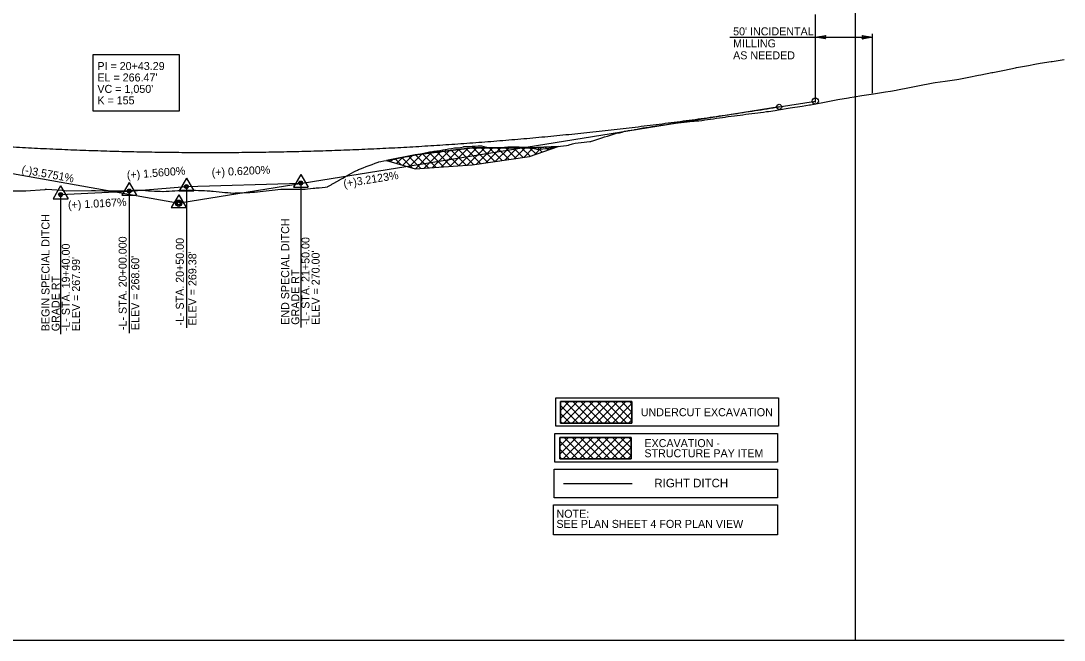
# Model space of a CAD drawing. Extents: x 10000 to 11818, y 10000 to 11025.
# Drawn here: x 10905 to 11818, y 10000 to 10542 of the extents above; entities that cross this region are included whole.
import ezdxf

# ---------------------------------------------------------------- set-up
doc = ezdxf.new("R2010")
doc.units = 0
for name, color, linetype in [('Exist Profile Cell', 7, 'Continuous'), ('Exist Vertical Profile Ground Line', 7, 'Continuous'), ('Old_Level_1', 7, 'Continuous'), ('Prop Grid Mask', 7, 'Continuous'), ('Prop PFL Ditch Label CELL', 7, 'Continuous'), ('Prop PFL VPI Symbol CELL', 7, 'Continuous'), ('Prop Terminator CELL', 7, 'Continuous'), ('Prop Vertical Profile Curve Label', 7, 'Continuous'), ('Prop Vertical Profile Ditch Grade Right', 7, 'Continuous'), ('Prop Vertical Profile Ditch Grade Right Label', 7, 'Continuous'), ('Prop Vertical Profile Grade', 7, 'Continuous'), ('Prop Vertical Profile Grade Label', 7, 'Continuous'), ('Prop VPI Ditch Grade Right Label', 7, 'Continuous'), ('Prop VPI Label', 7, 'Continuous'), ('Sheet Layout Profile Border', 7, 'Continuous'), ('Sheet Profile Grid Minor CELL', 7, 'Continuous')]:
    doc.layers.add(name, color=color, linetype=linetype)

msp = doc.modelspace()

# ---------------------------------------------------------------- linework, layer by layer
at = {"layer": 'Exist Profile Cell'}
msp.add_line((10000, 10000), (11817.54, 10000), dxfattribs=at)
at = {"layer": 'Exist Vertical Profile Ground Line'}
msp.add_lwpolyline([(10889.89, 10393.08), (10908.66, 10393.17), (10909.57, 10393.24), (10926.11, 10394.31), (10926.5, 10394.43), (10926.87, 10394.49), (10927.62, 10394.76), (10941.38, 10393.87), (10945.35, 10393.2), (10967.09, 10393.44), (10968.59, 10393.36), (10970.53, 10393.37), (10978.2, 10393.26), (10980.78, 10393.23), (10983.35, 10393.19), (10985.92, 10393.15), (10988.76, 10393.11), (10991.07, 10393.15), (10993.83, 10393.19), (10996.22, 10393.3), (10998.79, 10393.41), (11001.37, 10393.53), (11003.94, 10393.64), (11006.51, 10393.76), (11009.09, 10393.86), (11011.66, 10393.64), (11014.23, 10393.42), (11016.81, 10393.2), (11018, 10393.09), (11019.38, 10393.05), (11021.95, 10392.96), (11024.53, 10392.88), (11027.1, 10392.79), (11029.31, 10392.71), (11029.68, 10392.73), (11032.25, 10392.88), (11034.82, 10393.02), (11037.4, 10393.17), (11039.97, 10393.31), (11042.54, 10393.45), (11043.22, 10393.49), (11045.12, 10393.61), (11047.69, 10393.77), (11049.72, 10393.9), (11050.27, 10393.9), (11052.84, 10393.87), (11053.95, 10393.86), (11055.41, 10393.81), (11057.99, 10393.7), (11060.56, 10393.6), (11063.13, 10393.49), (11065.71, 10393.38), (11068.28, 10393.27), (11070.54, 10393.22), (11070.85, 10393.18), (11072.05, 10393.01), (11073.43, 10392.88), (11076, 10392.62), (11078.58, 10392.36), (11081.15, 10392.1), (11083.72, 10391.85), (11086.3, 10391.58), (11088.29, 10391.38), (11088.87, 10391.32), (11090.65, 10391.12), (11091.44, 10391.19), (11092.61, 10391.3), (11094.02, 10391.35), (11096.59, 10391.44), (11099.16, 10391.53), (11101.74, 10391.62), (11104.31, 10391.71), (11105.4, 10391.75), (11106.89, 10391.88), (11109.46, 10392.11), (11111.66, 10392.3), (11112.03, 10392.34), (11114.61, 10392.64), (11117.18, 10392.94), (11119.75, 10393.24), (11122.33, 10393.54), (11124.9, 10393.83), (11127.48, 10394.12), (11130.05, 10394.3), (11132.62, 10394.49), (11135.2, 10394.55), (11137.77, 10394.61), (11140.34, 10394.67), (11142.92, 10394.73), (11143.76, 10394.75), (11145.49, 10394.75), (11148.06, 10394.74), (11150.64, 10394.72), (11153.21, 10394.71), (11153.7, 10394.71), (11155.79, 10394.92), (11158.36, 10395.17), (11160.93, 10395.42), (11162.16, 10395.54), (11163.51, 10395.67), (11166.08, 10395.92), (11168.65, 10396.16), (11171.23, 10396.4), (11173.27, 10396.6), (11173.8, 10396.87), (11176.58, 10398.28), (11177.23, 10399.02), (11178.95, 10399.97), (11181.52, 10401.39), (11184.1, 10402.82), (11184.46, 10403.02), (11186.67, 10404.26), (11189.24, 10405.71), (11191.82, 10407.15), (11194.39, 10408.6), (11196.5, 10409.79), (11196.96, 10410.08), (11197.6, 10410.49), (11199.54, 10411.35), (11200.56, 10411.81), (11202.11, 10412.4), (11204.69, 10413.39), (11207.26, 10414.37), (11209.83, 10415.36), (11212.41, 10416.34), (11214.98, 10417.32), (11217.55, 10418.3), (11218.23, 10418.56), (11220.13, 10418.88), (11222.7, 10419.33), (11225.27, 10419.77), (11227.85, 10420.21), (11230.42, 10420.65), (11232.13, 10420.95), (11233, 10421.14), (11235.57, 10421.7), (11238.14, 10422.26), (11240.22, 10422.71), (11240.72, 10422.8), (11243.29, 10423.3), (11245.86, 10423.8), (11248.44, 10424.3), (11249.27, 10424.46), (11251.01, 10424.82), (11253.58, 10425.36), (11256.16, 10425.89), (11258.73, 10426.42), (11261.31, 10426.95), (11262.49, 10427.2), (11263.88, 10427.41), (11266.45, 10427.8), (11269.03, 10428.19), (11271.6, 10428.58), (11274.17, 10428.97), (11276.15, 10429.27), (11276.75, 10429.37), (11279.32, 10429.82), (11281.9, 10430.26), (11284.47, 10430.7), (11285.06, 10430.8), (11287.04, 10430.71), (11287.69, 10430.69), (11289.62, 10431.14), (11292.19, 10431.74), (11292.71, 10431.86), (11294.76, 10431.96), (11297.34, 10432.08), (11299.91, 10432.19), (11302.48, 10432.31), (11305.06, 10432.42), (11307.63, 10432.53), (11307.96, 10432.54), (11310.21, 10432.04), (11312.78, 10431.48), (11315.35, 10430.9), (11316.69, 10430.61), (11317.93, 10430.69), (11320.5, 10430.87), (11323.07, 10431.04), (11325.65, 10431.22), (11328.22, 10431.39), (11331.07, 10431.58), (11331.4, 10431.63), (11332.44, 10431.63), (11333.37, 10431.62), (11335.94, 10431.6), (11338.52, 10431.57), (11341.09, 10431.54), (11343.66, 10431.51), (11346.24, 10431.47), (11346.75, 10431.47), (11348.81, 10431.09), (11351.38, 10430.62), (11353.96, 10430.14), (11355.68, 10429.82), (11356.53, 10429.67), (11357.91, 10429.41), (11359.11, 10429.56), (11361.68, 10429.89), (11364.25, 10430.21), (11366.83, 10430.54), (11368.02, 10430.69), (11369.4, 10430.94), (11371.97, 10431.42), (11373.3, 10431.67), (11374.55, 10431.83), (11377.12, 10432.17), (11379.69, 10432.51), (11382.27, 10432.84), (11384.03, 10433.06), (11384.84, 10433.37), (11387.66, 10434.43), (11389.99, 10434.74), (11392.56, 10435.07), (11395.14, 10435.4), (11397.71, 10435.72), (11400.28, 10436.04), (11402.86, 10436.34), (11403.63, 10436.43), (11404.29, 10436.64), (11405.43, 10437.01), (11408, 10437.85), (11410.58, 10438.68), (11413.15, 10439.5), (11415.73, 10440.32), (11418.3, 10441.12), (11420.89, 10441.93), (11423.45, 10442.8), (11426.08, 10443.5), (11428.59, 10443.96), (11430.01, 10444.21), (11431.17, 10444.62), (11433.17, 10445.33), (11433.74, 10445.42), (11436.32, 10445.82), (11438.89, 10446.22), (11441.46, 10446.62), (11442.11, 10446.72), (11444.04, 10447.19), (11446.52, 10447.78), (11449.18, 10448.2), (11451.76, 10448.6), (11454.33, 10449), (11456.9, 10449.4), (11459.48, 10449.79), (11461.16, 10450.05), (11462.05, 10450.18), (11464.63, 10450.57), (11467.2, 10450.95), (11469.77, 10451.33), (11472.35, 10451.7), (11474.92, 10452.08), (11476.55, 10452.32), (11477.49, 10452.42), (11480.07, 10452.69), (11482.64, 10452.95), (11485.21, 10453.22), (11487.79, 10453.48), (11490.36, 10453.75), (11492.94, 10454.01), (11494.15, 10454.13), (11495.51, 10454.28), (11498.08, 10454.56), (11500.66, 10454.84), (11502.24, 10455.01), (11503.23, 10455.16), (11505.8, 10455.53), (11508.38, 10455.9), (11510.95, 10456.26), (11513.52, 10456.63), (11516.1, 10457), (11518.67, 10457.36), (11521.25, 10457.73), (11522.07, 10457.84), (11523.82, 10458.09), (11526.39, 10458.44), (11529.15, 10458.83), (11531.54, 10459.14), (11534.11, 10459.48), (11536.69, 10459.81), (11539.26, 10460.15), (11541.84, 10460.48), (11544.41, 10460.81), (11546.98, 10461.14), (11549.56, 10461.47), (11552.13, 10461.8), (11554.7, 10462.13), (11557.28, 10462.45), (11559.08, 10462.68), (11564.9, 10463.6), (11567.69, 10464.04), (11578.1, 10465.69), (11588.51, 10467.34), (11594.94, 10468.36), (11595.64, 10468.53), (11598.92, 10469.14), (11609.33, 10471.06), (11619.74, 10472.98), (11628.85, 10474.66), (11630.15, 10474.9), (11633.8, 10475.55), (11640.56, 10476.59), (11650.97, 10478.19), (11661.38, 10479.79), (11665.71, 10480.45), (11670.76, 10481.28), (11671.79, 10481.48), (11682.2, 10483.53), (11692.61, 10485.57), (11700.19, 10487.06), (11703.02, 10487.61), (11704.87, 10487.97), (11713.43, 10489.19), (11723.84, 10490.68), (11725.36, 10490.9), (11734.25, 10492.63), (11742.61, 10494.25), (11744.66, 10494.67), (11754.29, 10496.61), (11755.07, 10496.77), (11765.48, 10498.9), (11774.9, 10500.83), (11775.89, 10501.02), (11786.3, 10502.98), (11792.05, 10504.07), (11796.72, 10504.78), (11806.31, 10506.23), (11807.13, 10506.37), (11817.54, 10508.15)], dxfattribs=at)
at = {"layer": 'Old_Level_1'}
for p, q in [((11250, 10424.6), (11300, 10430.83)), ((11300, 10430.83), (11350, 10430.87)), ((11350, 10430.87), (11375, 10431.89)), ((11350, 10423.2), (11375, 10431.89)), ((11225, 10419.72), (11250, 10424.6)), ((11225, 10419.72), (11250, 10412.51)), ((11300, 10415.8), (11350, 10423.2)), ((11250, 10412.51), (11300, 10415.8)), ((11377.17, 10194.02), (11391.87, 10208.72)), ((11377.17, 10201.09), (11384.8, 10208.72)), ((11377.17, 10208.16), (11377.73, 10208.72)), ((11377.17, 10205.38), (11392.62, 10189.92)), ((11380.15, 10189.92), (11398.95, 10208.72)), ((11380.89, 10208.72), (11399.69, 10189.92)), ((11387.22, 10189.92), (11406.02, 10208.72)), ((11387.96, 10208.72), (11406.76, 10189.92)), ((11394.29, 10189.92), (11413.09, 10208.72)), ((11395.03, 10208.72), (11413.83, 10189.92)), ((11401.36, 10189.92), (11420.16, 10208.72)), ((11402.1, 10208.72), (11420.9, 10189.92)), ((11408.43, 10189.92), (11427.23, 10208.72)), ((11409.18, 10208.72), (11427.98, 10189.92)), ((11415.5, 10189.92), (11434.3, 10208.72)), ((11416.25, 10208.72), (11435.05, 10189.92)), ((11422.57, 10189.92), (11439.61, 10206.97)), ((11423.32, 10208.72), (11439.61, 10192.43)), ((11429.64, 10189.92), (11439.61, 10199.9)), ((11430.39, 10208.72), (11439.61, 10199.5)), ((11437.46, 10208.72), (11439.61, 10206.57)), ((11377.17, 10198.31), (11385.55, 10189.92)), ((11377.17, 10191.23), (11378.48, 10189.92)), ((11436.71, 10189.92), (11439.61, 10192.82)), ((11376.5, 10162.76), (11391.2, 10177.47)), ((11376.5, 10169.83), (11384.13, 10177.47)), ((11376.5, 10176.9), (11377.06, 10177.47)), ((11376.5, 10174.12), (11391.95, 10158.67)), ((11379.48, 10158.67), (11398.28, 10177.47)), ((11380.22, 10177.47), (11399.02, 10158.67)), ((11386.55, 10158.67), (11405.35, 10177.47)), ((11387.29, 10177.47), (11406.09, 10158.67)), ((11393.62, 10158.67), (11412.42, 10177.47)), ((11394.36, 10177.47), (11413.16, 10158.67)), ((11400.69, 10158.67), (11419.49, 10177.47)), ((11401.43, 10177.47), (11420.23, 10158.67)), ((11407.76, 10158.67), (11426.56, 10177.47)), ((11408.51, 10177.47), (11427.31, 10158.67)), ((11414.83, 10158.67), (11433.63, 10177.47)), ((11415.58, 10177.47), (11434.38, 10158.67)), ((11421.9, 10158.67), (11438.94, 10175.71)), ((11422.65, 10177.47), (11438.94, 10161.17)), ((11429.72, 10177.47), (11438.94, 10168.24)), ((11436.79, 10177.47), (11438.94, 10175.31)), ((11376.5, 10167.05), (11384.88, 10158.67)), ((11428.97, 10158.67), (11438.94, 10168.64)), ((11376.5, 10159.98), (11377.81, 10158.67)), ((11436.04, 10158.67), (11438.94, 10161.57))]:
    msp.add_line(p, q, dxfattribs=at)
for points in [[(11377.17, 10208.72), (11439.61, 10208.72), (11439.61, 10189.92), (11377.17, 10189.92)], [(11376.5, 10177.47), (11438.94, 10177.47), (11438.94, 10158.67), (11376.5, 10158.67)]]:
    msp.add_lwpolyline(points, close=True, dxfattribs=at)
for points in [[(11377.17, 10189.92), (11439.61, 10189.92), (11439.61, 10208.72), (11377.17, 10208.72), (11377.17, 10189.92)], [(11376.5, 10158.67), (11438.94, 10158.67), (11438.94, 10177.47), (11376.5, 10177.47), (11376.5, 10158.67)]]:
    msp.add_lwpolyline(points, dxfattribs=at)
at = {"layer": 'Prop Grid Mask'}
for points in [[(10968.58, 10512.58), (11043.68, 10512.58), (11043.68, 10462.87), (10968.58, 10462.87)], [(11372.97, 10212.13), (11567.63, 10212.13), (11567.63, 10187.13), (11372.97, 10187.13)], [(11372.3, 10180.88), (11566.96, 10180.88), (11566.96, 10155.88), (11372.3, 10155.88)], [(11371.63, 10149.62), (11566.96, 10149.62), (11566.96, 10124.62), (11371.63, 10124.62)], [(11370.96, 10118.36), (11566.96, 10118.36), (11566.96, 10092.28), (11370.96, 10092.28)]]:
    msp.add_lwpolyline(points, close=True, dxfattribs=at)
at = {"layer": 'Prop PFL Ditch Label CELL'}
for p, q in [((11372.97, 10197.13), (11372.97, 10197.13)), ((11372.3, 10165.88), (11372.3, 10165.88)), ((11379.71, 10136.97), (11439.71, 10136.97)), ((11371.63, 10134.62), (11371.63, 10134.62))]:
    msp.add_line(p, q, dxfattribs=at)
at = {"layer": 'Prop PFL VPI Symbol CELL'}
for p, q in [((10999.99, 10400.48), (10993.54, 10389.28)), ((10999.99, 10400.48), (11006.49, 10389.28)), ((11049.99, 10404.38), (11043.54, 10393.18)), ((11049.99, 10404.38), (11056.49, 10393.18)), ((11149.99, 10407.48), (11143.54, 10396.28)), ((11149.99, 10407.48), (11156.49, 10396.28)), ((10939.99, 10397.43), (10933.54, 10386.23)), ((10939.99, 10397.43), (10946.49, 10386.23)), ((11043.54, 10393.18), (11056.49, 10393.18)), ((11143.54, 10396.28), (11156.49, 10396.28)), ((10933.54, 10386.23), (10946.49, 10386.23)), ((10993.54, 10389.28), (11006.49, 10389.28)), ((11043.24, 10389.68), (11036.79, 10378.48)), ((11043.24, 10389.68), (11049.74, 10378.48)), ((11036.79, 10378.48), (11049.74, 10378.48))]:
    msp.add_line(p, q, dxfattribs=at)
for centre, radius in [((11150, 10400), 1.75), ((11150, 10400), 1.2), ((10940, 10389.95), 1.75), ((11000, 10393), 1.75), ((11000, 10393), 1.2), ((11050, 10396.9), 1.75), ((11050, 10396.9), 1.2), ((10940, 10389.95), 1.2), ((11043.25, 10382.2), 1.75), ((11043.25, 10382.2), 1.2)]:
    msp.add_circle(centre, radius, dxfattribs=at)
at = {"layer": 'Prop Terminator CELL'}
for points in [[(11609, 10526.04), (11600, 10527.59), (11609.05, 10529.19), (11607.9, 10527.59)], [(11641, 10529.14), (11650, 10527.59), (11640.95, 10525.99), (11642.1, 10527.59)]]:
    msp.add_lwpolyline(points, close=True, dxfattribs=at)
at = {"layer": 'Prop Vertical Profile Curve Label'}
msp.add_circle((11568.29, 10466.66), 2.25, dxfattribs=at)
at = {"layer": 'Prop Vertical Profile Ditch Grade Right'}
msp.add_lwpolyline([(10940, 10389.95), (11000, 10393), (11050, 10396.9), (11150, 10400)], dxfattribs=at)
at = {"layer": 'Prop Vertical Profile Ditch Grade Right Label'}
for p, q in [((11000, 10393), (11000, 10268.58)), ((11050, 10396.9), (11050, 10273.22)), ((11150, 10400), (11150, 10273.5)), ((10940, 10389.95), (10940, 10267.77))]:
    msp.add_line(p, q, dxfattribs=at)
at = {"layer": 'Prop Vertical Profile Grade'}
msp.add_line((11568.29, 10466.66), (11600, 10471.75), dxfattribs=at)
msp.add_spline([(10518.29, 10476.18), (10539.29, 10472.5), (10560.29, 10468.96), (10581.29, 10465.56), (10602.29, 10462.3), (10623.29, 10459.19), (10644.29, 10456.22), (10665.29, 10453.4), (10686.29, 10450.71), (10707.29, 10448.17), (10728.29, 10445.77), (10749.29, 10443.51), (10770.29, 10441.4), (10791.29, 10439.42), (10812.29, 10437.59), (10833.29, 10435.91), (10854.29, 10434.36), (10875.29, 10432.96), (10896.29, 10431.7), (10917.29, 10430.58), (10938.29, 10429.61), (10959.29, 10428.78), (10980.29, 10428.09), (11001.29, 10427.54), (11022.29, 10427.14), (11043.29, 10426.88), (11064.29, 10426.76), (11085.29, 10426.78), (11106.29, 10426.95), (11127.29, 10427.25), (11148.29, 10427.71), (11169.29, 10428.3), (11190.29, 10429.04), (11211.29, 10429.91), (11232.29, 10430.93), (11253.29, 10432.1), (11274.29, 10433.4), (11295.29, 10434.85), (11316.29, 10436.44), (11337.29, 10438.18), (11358.29, 10440.05), (11379.29, 10442.07), (11400.29, 10444.23), (11421.29, 10446.54), (11442.29, 10448.99), (11463.29, 10451.57), (11484.29, 10454.31), (11505.29, 10457.18), (11526.29, 10460.2), (11547.29, 10463.36), (11568.29, 10466.66)], degree=3, dxfattribs=at)
at = {"layer": 'Prop VPI Ditch Grade Right Label'}
for centre in [(11150, 10400), (10940, 10389.95)]:
    msp.add_circle(centre, 0.5, dxfattribs=at)
at = {"layer": 'Prop VPI Label'}
for p, q in [((11600, 10470.59), (11600, 10547.5)), ((11650, 10478.58), (11650, 10530.58)), ((11525.08, 10527.59), (11600, 10527.59)), ((11600, 10527.59), (11650, 10527.59)), ((10518.29, 10476.18), (11040.58, 10382.82)), ((11568.29, 10466.66), (11046.01, 10382.77))]:
    msp.add_line(p, q, dxfattribs=at)
for centre in [(11600, 10471.75), (11043.29, 10382.33)]:
    msp.add_circle(centre, 2.75, dxfattribs=at)
at = {"layer": 'Sheet Layout Profile Border'}
msp.add_lwpolyline([(10250, 11025), (10250, 10000), (10250, 10000), (11635, 10000), (11635, 10000), (11635, 10887.45), (11635, 10887.45), (11492.45, 10887.45), (11492.45, 11025)], close=True, dxfattribs=at)
at = {"layer": 'Sheet Profile Grid Minor CELL'}
for p, q in [((11300, 10430.83), (11250, 10424.6)), ((11265.33, 10413.51), (11280.17, 10428.36)), ((11272.9, 10414.01), (11288.25, 10429.36)), ((11275.42, 10427.77), (11288.17, 10415.02)), ((11280.47, 10414.51), (11296.33, 10430.37)), ((11281.71, 10428.55), (11294.81, 10415.45)), ((11288, 10429.33), (11301.34, 10415.99)), ((11288.04, 10415.01), (11303.86, 10430.83)), ((11294.29, 10430.11), (11307.5, 10416.91)), ((11295.61, 10415.51), (11310.94, 10430.83)), ((11350, 10430.87), (11300, 10430.83)), ((11300.65, 10430.83), (11313.66, 10417.82)), ((11303.48, 10416.31), (11318.01, 10430.84)), ((11307.71, 10430.83), (11319.82, 10418.73)), ((11311.78, 10417.54), (11325.09, 10430.85)), ((11314.78, 10430.84), (11325.97, 10419.64)), ((11320.08, 10418.77), (11332.17, 10430.85)), ((11321.84, 10430.84), (11332.13, 10420.55)), ((11328.38, 10420), (11339.25, 10430.86)), ((11328.91, 10430.85), (11338.29, 10421.47)), ((11335.97, 10430.86), (11344.45, 10422.38)), ((11336.68, 10421.23), (11346.32, 10430.87)), ((11343.04, 10430.86), (11350.52, 10423.38)), ((11344.99, 10422.46), (11353.54, 10431.02)), ((11350, 10423.2), (11375, 10431.89)), ((11375, 10431.89), (11350, 10430.87)), ((11350.1, 10430.87), (11355.77, 10425.21)), ((11354.29, 10424.69), (11360.92, 10431.32)), ((11356.89, 10431.15), (11361.01, 10427.03)), ((11363.68, 10431.43), (11366.26, 10428.85)), ((11365.13, 10428.46), (11368.29, 10431.62)), ((11370.48, 10431.71), (11371.51, 10430.68)), ((11250, 10424.6), (11225, 10419.72)), ((11225, 10419.72), (11250, 10412.51)), ((11226.59, 10420.03), (11227.67, 10418.95)), ((11228.19, 10418.8), (11230.11, 10420.72)), ((11232.51, 10421.19), (11237.61, 10416.08)), ((11233.68, 10417.22), (11238.9, 10422.43)), ((11238.42, 10422.34), (11247.55, 10413.21)), ((11239.17, 10415.63), (11247.68, 10424.15)), ((11244.34, 10423.5), (11255, 10412.83)), ((11244.65, 10414.05), (11255.94, 10425.34)), ((11250.19, 10412.52), (11264.02, 10426.35)), ((11250.27, 10424.63), (11261.63, 10413.27)), ((11256.56, 10425.42), (11268.27, 10413.71)), ((11257.76, 10413.02), (11272.1, 10427.35)), ((11262.85, 10426.2), (11274.9, 10414.14)), ((11269.14, 10426.98), (11281.54, 10414.58)), ((11300, 10415.8), (11350, 10423.2)), ((11250, 10412.51), (11300, 10415.8))]:
    msp.add_line(p, q, dxfattribs=at)

# ---------------------------------------------------------------- texts
at = {"layer": 'Prop PFL Ditch Label CELL'}
for s, height, p in [('UNDERCUT EXCAVATION ', 7, (11447.35, 10195.96)), ('EXCAVATION -', 7, (11450.5, 10168.91)), ('STRUCTURE PAY ITEM', 7, (11450.5, 10160.03)), ('RIGHT DITCH', 7.485, (11459.21, 10133.72))]:
    msp.add_text(s, height=height, dxfattribs=at).set_placement(p)
at = {"layer": 'Prop Vertical Profile Curve Label'}
for s, p in [("VC = 1,050'", (10972.14, 10478.86)), ('K = 155', (10972.14, 10468.86))]:
    msp.add_text(s, height=7, dxfattribs=at).set_placement(p)
at = {"layer": 'Prop Vertical Profile Ditch Grade Right Label'}
for s, rotation, p in [('(+) 1.5600%', 4.46004, (10998.15, 10403.47)), ('(+) 0.6200%', 2.69092, (11072.24, 10405.84)), ('(+) 1.0167%', 2.91003, (10946.6, 10377.34))]:
    msp.add_text(s, height=7, rotation=rotation, dxfattribs=at).set_placement(p)
at = {"layer": 'Prop Vertical Profile Grade Label'}
for s, rotation, p in [('(-)3.5751%', 349.8652, (10905.44, 10408.59)), ('(+)3.2123%', 9.12463, (11187.86, 10395.96))]:
    msp.add_text(s, height=7, rotation=rotation, dxfattribs=at).set_placement(p)
at = {"layer": 'Prop VPI Ditch Grade Right Label'}
for s, p in [('BEGIN SPECIAL DITCH', (10930.26, 10270.3)), ('END SPECIAL DITCH', (11139.85, 10275.94)), ('-L- STA. 19+40.00', (10948.01, 10270.3)), ('-L- STA. 20+00.000', (10997.73, 10271.34)), ('-L- STA. 20+50.00', (11047.73, 10275.24)), ('-L- STA. 21+50.00', (11157.6, 10275.94)), ("ELEV = 269.38'", (11058.73, 10275.24)), ("ELEV = 270.00'", (11166.47, 10275.94)), ("ELEV = 267.99'", (10956.88, 10270.3)), ("ELEV = 268.60'", (11008.73, 10271.34)), ('GRADE RT', (10939.14, 10270.3)), ('GRADE RT', (11148.72, 10275.94))]:
    msp.add_text(s, height=7, rotation=90, dxfattribs=at).set_placement(p)
at = {"layer": 'Prop VPI Label'}
for s, p in [("50' INCIDENTAL", (11528.06, 10529.21)), ('MILLING', (11528.06, 10518.71)), ('AS NEEDED', (11528.06, 10508.21))]:
    msp.add_text(s, height=7, rotation=360, dxfattribs=at).set_placement(p)
for s, p in [('PI = 20+43.29', (10972.14, 10498.86)), ("EL = 266.47'", (10972.14, 10488.86)), ('NOTE:', (11373.58, 10107.09)), ('SEE PLAN SHEET 4 FOR PLAN VIEW', (11373.58, 10098.22))]:
    msp.add_text(s, height=7, dxfattribs=at).set_placement(p)

doc.saveas('drawing.dxf')
